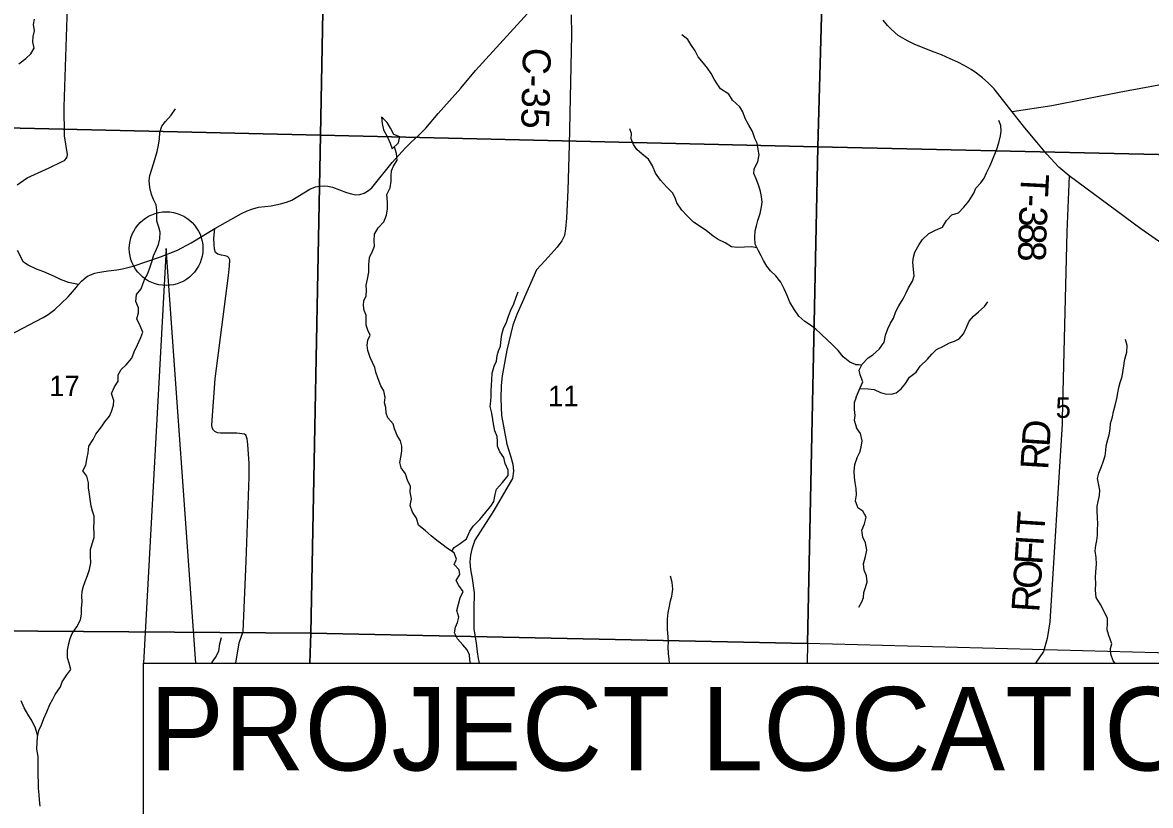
# Model space of a CAD drawing. Extents: x -20.5 to 34, y -66 to 23.9.
# Drawn here: x 3.275 to 5.573, y 15.05 to 16.645 of the extents above; entities that cross this region are included whole.
import ezdxf

# ---------------------------------------------------------------- set-up
doc = ezdxf.new("R2010")
doc.units = 0
for name, color, linetype in [('GM_X_County_Text', 7, 'Continuous'), ('GM_X_Minor_Lake', 7, 'Continuous'), ('GM_X_Minor_River', 7, 'Continuous'), ('GM_X_Minor_River_Text', 7, 'Continuous'), ('GM_X_Section_Text', 7, 'Continuous'), ('GM_X_State_Route', 7, 'Continuous'), ('GM_X_Township_Road', 7, 'Continuous'), ('GM_X_Township_Road_Text', 7, 'Continuous'), ('GM_X_Township_Text', 7, 'Continuous'), ('SH_Text', 7, 'Continuous')]:
    doc.layers.add(name, color=color, linetype=linetype)

msp = doc.modelspace()

# ---------------------------------------------------------------- linework, layer by layer
at = {"layer": 'GM_X_County_Text'}
for points in [[(3.2635, 16.3144), (3.2839, 16.3283), (3.3288, 16.3487), (3.3542, 16.3609), (3.3599, 16.3637), (3.3646, 16.3694), (3.3636, 16.3694), (3.3655, 16.3713), (3.3663, 16.3761), (3.3602, 16.4143), (3.3594, 16.4735), (3.3718, 16.8405), (3.3957, 16.9949), (3.3943, 17.0069), (3.3923, 17.02), (3.3913, 17.0343), (3.3936, 17.0515), (3.396, 17.073), (3.3943, 17.0819)], [(5.6962, 16.5372), (5.5091, 16.5021), (5.372, 16.4751), (5.2911, 16.4627)], [(5.4069, 16.3325), (5.4025, 16.2189), (5.3927, 15.8374)], [(3.7094, 15.34), (3.7163, 15.3814), (3.7239, 15.4048), (3.7302, 15.5476), (3.7366, 15.7189), (3.7361, 15.747), (3.7334, 15.7853), (3.733, 15.7913), (3.7324, 15.7967), (3.7308, 15.8011), (3.7297, 15.8044), (3.7271, 15.8068), (3.7115, 15.8086), (3.6781, 15.8083), (3.672, 15.8093), (3.6665, 15.812), (3.6638, 15.8143), (3.6611, 15.8197), (3.6605, 15.8256), (3.6674, 15.9189), (3.6941, 16.1299), (3.6966, 16.1487), (3.6973, 16.1613), (3.6952, 16.1654), (3.692, 16.1685), (3.6872, 16.1694), (3.6799, 16.1711), (3.6727, 16.173), (3.6681, 16.1762), (3.6654, 16.183), (3.6648, 16.193), (3.6646, 16.2059), (3.6667, 16.2252)], [(3.3886, 16.1111), (3.3681, 16.1151), (3.3519, 16.1215), (3.3395, 16.1275), (3.318, 16.1368), (3.3029, 16.1426), (3.2859, 16.1508), (3.2765, 16.1565), (3.2643, 16.1803)], [(5.3927, 15.8374), (5.3925, 15.8275), (5.3674, 15.4243), (5.3621, 15.3903), (5.3547, 15.3635), (5.3386, 15.34)]]:
    msp.add_lwpolyline(points, dxfattribs=at)
at = {"layer": 'GM_X_Minor_Lake'}
for points in [[(4.5524, 17.4637), (4.898, 17.4556), (4.9246, 17.4548), (4.8948, 16.3916), (3.8817, 16.4153), (3.8974, 17.2409)], [(3.8974, 17.2409), (3.8817, 16.4153), (2.8609, 16.4392), (2.8718, 17.2409)], [(3.8345, 14.5564), (3.829, 14.3877), (2.8293, 14.4033), (2.8417, 15.4083), (3.8622, 15.401), (3.8602, 15.34)], [(3.8602, 15.34), (3.8622, 15.401), (4.8742, 15.38), (4.8734, 15.34)]]:
    msp.add_lwpolyline(points, dxfattribs=at)
for points in [[(4.9246, 17.4548), (5.9103, 17.4412), (5.9082, 17.3615), (5.9397, 17.3613), (5.9209, 16.3687), (4.8948, 16.3916)], [(3.8817, 16.4153), (3.8622, 15.401), (2.8417, 15.4083), (2.8609, 16.4392)], [(4.8948, 16.3916), (4.8742, 15.38), (3.8622, 15.401), (3.8817, 16.4153)], [(4.8948, 16.3916), (5.9209, 16.3687), (5.8926, 15.3531), (4.8742, 15.38)]]:
    msp.add_lwpolyline(points, close=True, dxfattribs=at)
at = {"layer": 'GM_X_Minor_River'}
for points in [[(4.0087, 16.4498), (4.0062, 16.4523), (4.0076, 16.4391), (4.01, 16.4262), (4.0175, 16.4131), (4.0238, 16.3995), (4.0277, 16.3875)], [(4.0277, 16.3875), (4.0404, 16.3998), (4.0436, 16.412), (4.0314, 16.4171), (4.024, 16.4295), (4.0174, 16.4415), (4.0087, 16.4498)]]:
    msp.add_lwpolyline(points, dxfattribs=at)
at = {"layer": 'GM_X_Minor_River_Text'}
for points in [[(3.2673, 16.561), (3.2815, 16.5714), (3.2916, 16.5811), (3.2986, 16.5926), (3.2957, 16.6054), (3.2966, 16.6168), (3.2987, 16.6278), (3.297, 16.6411), (3.2987, 16.6517)], [(4.9718, 15.9482), (4.9602, 15.9533), (4.9464, 15.9641), (4.9364, 15.9772), (4.9244, 15.9891), (4.9144, 15.9977), (4.901, 16.0111), (4.8906, 16.0204), (4.8799, 16.0282), (4.8684, 16.0363), (4.8561, 16.0467), (4.8475, 16.0598), (4.8378, 16.0756), (4.8323, 16.0892), (4.8264, 16.1023), (4.8193, 16.1159), (4.8096, 16.129), (4.7985, 16.139), (4.7911, 16.1488), (4.7845, 16.16), (4.7798, 16.1698), (4.774, 16.1799), (4.7673, 16.1935), (4.7663, 16.2071), (4.7672, 16.2208), (4.7697, 16.2307), (4.7725, 16.2417), (4.7776, 16.2562), (4.78, 16.2692), (4.7814, 16.2787), (4.78, 16.2904), (4.7783, 16.3006), (4.7747, 16.3123), (4.7696, 16.3266), (4.7645, 16.3371), (4.7651, 16.347), (4.7724, 16.3612), (4.7752, 16.3752), (4.7731, 16.3862), (4.7714, 16.3991), (4.7667, 16.4088), (4.7615, 16.4232), (4.7541, 16.4359), (4.7467, 16.4495), (4.7419, 16.463), (4.7357, 16.4731), (4.721, 16.4865), (4.7133, 16.4993), (4.6964, 16.5096), (4.6898, 16.5198), (4.684, 16.5295), (4.6777, 16.5408), (4.6703, 16.552), (4.6618, 16.5621), (4.6514, 16.5748), (4.6451, 16.5872), (4.6362, 16.6003), (4.6303, 16.6101), (4.6181, 16.6201)], [(3.424, 15.8063), (3.4358, 15.8213), (3.4425, 15.8313), (3.4517, 15.8429), (3.4561, 15.8528), (3.4597, 15.8658), (3.4607, 15.8753), (3.4559, 15.8892), (3.4617, 15.903), (3.4698, 15.9141), (3.4696, 15.9274), (3.4755, 15.9385), (3.4856, 15.9474), (3.4971, 15.9616), (3.5021, 15.9742), (3.5087, 15.9883), (3.5157, 16.0033), (3.5196, 16.0139), (3.5145, 16.0268), (3.5078, 16.0411), (3.511, 16.0536), (3.5112, 16.0639), (3.5053, 16.077), (3.5066, 16.0907), (3.5163, 16.1023), (3.5195, 16.1122), (3.5235, 16.1229), (3.529, 16.1324), (3.533, 16.1431), (3.5384, 16.1595), (3.5412, 16.1698), (3.5474, 16.1832), (3.5514, 16.1927), (3.5543, 16.2045), (3.5548, 16.2178), (3.552, 16.2284), (3.5484, 16.2405), (3.5485, 16.2518), (3.548, 16.2625), (3.547, 16.2738), (3.5416, 16.2847), (3.5372, 16.2949), (3.5339, 16.3088), (3.5326, 16.3232), (3.5339, 16.3335), (3.5379, 16.3465), (3.5422, 16.3594), (3.5458, 16.3705), (3.549, 16.3819), (3.5514, 16.3948), (3.5535, 16.4078), (3.5544, 16.4211), (3.5587, 16.434), (3.5657, 16.4436), (3.5772, 16.4563), (3.5865, 16.469)], [(4.9728, 15.882), (4.9811, 15.9008), (4.9863, 15.9134), (4.9811, 15.927), (4.9791, 15.9368), (4.985, 15.9491), (4.9973, 15.9618), (5.007, 15.9684), (5.0204, 15.9804), (5.0301, 15.9938), (5.0329, 16.0079), (5.0376, 16.0208), (5.0431, 16.0323), (5.049, 16.0427), (5.0541, 16.0564), (5.06, 16.0682), (5.0685, 16.0824), (5.0751, 16.0943), (5.0799, 16.1042), (5.088, 16.1184), (5.0913, 16.1287), (5.0896, 16.1416), (5.0886, 16.1571), (5.0899, 16.167), (5.0928, 16.1773), (5.1017, 16.1926), (5.1079, 16.2033), (5.1214, 16.2149), (5.1345, 16.2219), (5.1488, 16.2282), (5.1573, 16.2416), (5.1677, 16.2532), (5.1817, 16.2572), (5.1925, 16.2691), (5.2029, 16.281), (5.2125, 16.2975), (5.2165, 16.3074), (5.2273, 16.3182), (5.2339, 16.3282), (5.2387, 16.3389), (5.2453, 16.3523), (5.2497, 16.3622), (5.2537, 16.3721), (5.2588, 16.3847), (5.2635, 16.3996), (5.2671, 16.4141), (5.2685, 16.4236), (5.2675, 16.4353), (5.2636, 16.4451)], [(4.7711, 16.1858), (4.7598, 16.188), (4.7454, 16.1874), (4.7307, 16.1868), (4.7189, 16.1881), (4.7059, 16.1962), (4.6922, 16.2028), (4.6818, 16.2098), (4.6677, 16.221), (4.6416, 16.238), (4.6301, 16.2499), (4.6181, 16.2626), (4.6076, 16.2776), (4.6041, 16.2878), (4.5986, 16.2979), (4.5863, 16.3106), (4.5747, 16.324), (4.5642, 16.3379), (4.5583, 16.3533), (4.5497, 16.3668), (4.5367, 16.3765), (4.5263, 16.3865), (4.5197, 16.3963), (4.5149, 16.4083), (4.5151, 16.4186), (4.5116, 16.4284)], [(4.0104, 15.8945), (4.0049, 15.9051), (3.999, 15.919), (3.9946, 15.9326), (3.9925, 15.9424), (3.9831, 15.9627), (3.9779, 15.9771), (3.9766, 15.9877), (3.9783, 15.9979), (3.9827, 16.0079), (3.9784, 16.018), (3.9748, 16.0282), (3.975, 16.0388), (3.9748, 16.0487), (3.9709, 16.0585), (3.9692, 16.0683), (3.9702, 16.0778), (3.9745, 16.0885), (3.9755, 16.0999), (3.9745, 16.1097), (3.9774, 16.1223), (3.9802, 16.1364), (3.9799, 16.1512), (3.9812, 16.1664), (3.9878, 16.1794), (3.9917, 16.1893), (3.9912, 16.2003), (3.9917, 16.2139), (3.9991, 16.2266), (4.011, 16.2393), (4.0164, 16.2523), (4.0181, 16.2652), (4.0182, 16.2789), (4.0165, 16.2948), (4.0238, 16.3082), (4.0255, 16.3215), (4.0256, 16.3332), (4.0266, 16.3427), (4.0302, 16.3522), (4.0376, 16.3649), (4.0366, 16.3781), (4.0322, 16.3918)], [(4.1494, 15.568), (4.1538, 15.5757), (4.1662, 15.5835), (4.1793, 15.5936), (4.1858, 15.6088), (4.1929, 15.6192), (4.2063, 15.6327), (4.2185, 15.6477), (4.2285, 15.66), (4.2348, 15.6696), (4.2376, 15.6833), (4.2404, 15.6944), (4.2527, 15.7079), (4.2638, 15.7225), (4.264, 15.7331), (4.2581, 15.747), (4.2549, 15.7591), (4.2471, 15.7708), (4.242, 15.7817), (4.2422, 15.7915), (4.2417, 15.8018), (4.2366, 15.8135), (4.2345, 15.8233), (4.231, 15.849), (4.2274, 15.863), (4.2284, 15.8736), (4.2293, 15.8831), (4.2295, 15.8941), (4.2301, 15.9063), (4.2307, 15.9173), (4.2316, 15.931), (4.2355, 15.9451), (4.2402, 15.9554), (4.2419, 15.9668), (4.2444, 15.9763), (4.2481, 15.9859), (4.2497, 15.9999), (4.2514, 16.0098), (4.2543, 16.022), (4.2605, 16.0346), (4.2648, 16.0465), (4.2688, 16.0575), (4.2754, 16.072), (4.2804, 16.0858), (4.2844, 16.0961)], [(4.9807, 15.8997), (4.9974, 15.8988), (5.0096, 15.8974), (5.0229, 15.8912), (5.0324, 15.8883), (5.0449, 15.8881), (5.0547, 15.8909), (5.0644, 15.899), (5.0733, 15.9094), (5.0815, 15.9224), (5.0953, 15.9329), (5.1031, 15.9448), (5.1184, 15.9591), (5.1269, 15.9691), (5.137, 15.9787), (5.1509, 15.9858), (5.1633, 15.9924), (5.1731, 15.996), (5.1832, 16.0007), (5.1914, 16.0107), (5.1973, 16.0225), (5.2035, 16.0367), (5.2121, 16.047), (5.2221, 16.0555), (5.2348, 16.0667), (5.2415, 16.0763)], [(5.5008, 15.34), (5.4967, 15.3451), (5.4916, 15.3584), (5.4911, 15.3701), (5.4936, 15.3797), (5.488, 15.3963), (5.4845, 15.4076), (5.485, 15.4217), (5.4849, 15.4312), (5.4786, 15.4451), (5.4708, 15.4598), (5.4623, 15.4738), (5.4606, 15.4885), (5.4611, 15.5026), (5.4609, 15.5147), (5.4615, 15.5258), (5.4624, 15.5417), (5.4619, 15.5554), (5.4602, 15.569), (5.4615, 15.5797), (5.4633, 15.5896), (5.4646, 15.601), (5.4648, 15.612), (5.4654, 15.6234), (5.4648, 15.6367), (5.4643, 15.6496), (5.4637, 15.6595), (5.4663, 15.6694), (5.4691, 15.6816), (5.4697, 15.6926), (5.4673, 15.7028), (5.4648, 15.7164), (5.4677, 15.7267), (5.4731, 15.7409), (5.476, 15.7504), (5.48, 15.7626), (5.4814, 15.7733), (5.4827, 15.7828), (5.4856, 15.7954), (5.4885, 15.8053), (5.4902, 15.8167), (5.4915, 15.8285), (5.4951, 15.8418), (5.4976, 15.8529), (5.5005, 15.8647), (5.504, 15.8792), (5.5061, 15.8906), (5.5082, 15.9012), (5.5111, 15.9119), (5.5147, 15.9237), (5.5172, 15.9371), (5.5206, 15.9591), (5.5242, 15.9736), (5.5251, 15.9873), (5.5215, 15.9994)], [(4.9718, 15.9482), (4.9779, 15.9485), (4.9842, 15.9474)], [(4.1873, 15.34), (4.186, 15.347), (4.1851, 15.3568), (4.1804, 15.367), (4.1715, 15.3771), (4.1607, 15.3894), (4.1548, 15.4019), (4.1565, 15.4133), (4.1605, 15.4228), (4.1638, 15.4335), (4.1594, 15.4471), (4.1665, 15.473), (4.1724, 15.4857), (4.1635, 15.498), (4.1584, 15.5086), (4.1654, 15.5205), (4.1644, 15.5303), (4.154, 15.5408), (4.1588, 15.5518), (4.154, 15.565), (4.1402, 15.5739), (4.1291, 15.5821), (4.1188, 15.5899), (4.1073, 15.5991), (4.0954, 15.6096), (4.0816, 15.6211), (4.0772, 15.6351), (4.0694, 15.6478), (4.0646, 15.661), (4.067, 15.6747), (4.0645, 15.6883), (4.0651, 15.6997), (4.0592, 15.7129), (4.0548, 15.7257), (4.0463, 15.7377), (4.0435, 15.7487), (4.0463, 15.7628), (4.0472, 15.7723), (4.0471, 15.7817), (4.0446, 15.7927), (4.038, 15.8036), (4.0325, 15.8175), (4.0297, 15.8274), (4.0192, 15.8397), (4.0157, 15.8495), (4.0147, 15.8605), (4.0123, 15.8703), (4.0136, 15.8813), (4.0104, 15.8945)], [(4.9728, 15.882), (4.9688, 15.8704), (4.9691, 15.8567), (4.9704, 15.8442), (4.969, 15.8347), (4.9737, 15.8196)], [(4.9741, 15.7574), (4.9806, 15.7697), (4.9832, 15.7801), (4.9854, 15.7927), (4.9822, 15.8075), (4.9737, 15.8196)], [(3.3105, 15.0489), (3.3092, 15.0614), (3.3082, 15.072), (3.3073, 15.0853), (3.307, 15.0982), (3.3065, 15.11), (3.3062, 15.1259), (3.3064, 15.138), (3.3062, 15.1498), (3.3037, 15.1646), (3.3042, 15.179), (3.3052, 15.1893), (3.308, 15.2026), (3.3131, 15.2141), (3.3178, 15.2274), (3.324, 15.2408), (3.3305, 15.2561), (3.3364, 15.2668), (3.3408, 15.2764), (3.3519, 15.2918), (3.3555, 15.3017), (3.3647, 15.3163), (3.3729, 15.327), (3.3693, 15.3402), (3.3664, 15.3508), (3.3662, 15.3664), (3.369, 15.3801), (3.3715, 15.3904), (3.3755, 15.4003), (3.3851, 15.4141), (3.3924, 15.4283), (3.3945, 15.4401), (3.3947, 15.4511), (3.3963, 15.4659), (3.3954, 15.4758), (3.3964, 15.4868), (3.3988, 15.4967), (3.4021, 15.5066), (3.4068, 15.5188), (3.4111, 15.5311), (3.4139, 15.5444), (3.4133, 15.558), (3.4131, 15.5717), (3.4163, 15.5831), (3.4203, 15.5957), (3.4209, 15.6056), (3.4196, 15.6154), (3.4205, 15.6287), (3.4203, 15.6394), (3.4171, 15.6499), (3.4147, 15.6601), (3.4122, 15.6741), (3.4109, 15.684), (3.4087, 15.6972), (3.4093, 15.7075), (3.4057, 15.7207), (3.3976, 15.7315), (3.4034, 15.7434), (3.4066, 15.759), (3.4083, 15.7685), (3.41, 15.7822), (3.4185, 15.7956), (3.424, 15.8063)], [(4.9741, 15.7574), (4.9694, 15.7437), (4.9685, 15.7308), (4.9687, 15.7179), (4.9704, 15.708), (4.9721, 15.6955), (4.9727, 15.683), (4.971, 15.6705), (4.9764, 15.6567)], [(4.9788, 15.4539), (4.9844, 15.4652), (4.9878, 15.4737), (4.9888, 15.484), (4.992, 15.4939), (4.9953, 15.5058), (4.994, 15.5179), (4.9893, 15.5292), (4.9879, 15.5425), (4.9923, 15.557), (4.9951, 15.5703), (4.9918, 15.5851), (4.9868, 15.5968), (4.9843, 15.6108), (4.9898, 15.6238), (4.9933, 15.6375), (4.9864, 15.6493), (4.9764, 15.6567)], [(4.593, 15.34), (4.5918, 15.3479), (4.5908, 15.36), (4.5902, 15.3729), (4.5904, 15.3835), (4.5899, 15.3934), (4.5885, 15.4085), (4.5887, 15.4184), (4.5889, 15.4294), (4.5902, 15.4431), (4.592, 15.4526), (4.5947, 15.4667), (4.5976, 15.4762), (4.5996, 15.4907), (4.5983, 15.504), (4.595, 15.5172)], [(3.6607, 15.34), (3.6611, 15.3422), (3.6677, 15.3518), (3.6743, 15.3644), (3.6767, 15.3793), (3.6799, 15.3922)], [(3.3056, 15.1914), (3.3007, 15.2078), (3.294, 15.2221), (3.2851, 15.2363), (3.278, 15.2491), (3.2721, 15.2631)]]:
    msp.add_lwpolyline(points, dxfattribs=at)
at = {"layer": 'GM_X_State_Route'}
msp.add_lwpolyline([(4.3922, 16.6604), (4.393, 16.62), (4.388, 16.3949), (4.3858, 16.3032), (4.383, 16.2466), (4.3807, 16.2244), (4.3789, 16.2112), (4.3734, 16.2004), (4.3642, 16.1874), (4.3395, 16.1602), (4.3219, 16.141), (4.2923, 16.0746), (4.2819, 16.0505), (4.2735, 16.0282), (4.2613, 15.9778), (4.2517, 15.9256), (4.2501, 15.9053), (4.2488, 15.879), (4.2506, 15.8442), (4.2613, 15.786), (4.2689, 15.7626), (4.2736, 15.7454), (4.2748, 15.7309), (4.2732, 15.716), (4.2596, 15.6928), (4.2347, 15.6513), (4.1959, 15.5904), (4.1899, 15.572), (4.1873, 15.5598), (4.1859, 15.5464), (4.1871, 15.5305), (4.1904, 15.5126), (4.1946, 15.4835), (4.1939, 15.4497), (4.1939, 15.4224), (4.1941, 15.4093), (4.1986, 15.3815), (4.2006, 15.3629), (4.2026, 15.3498), (4.205, 15.34)], dxfattribs=at)
at = {"layer": 'GM_X_Township_Road'}
for points in [[(3.2186, 15.9933), (3.3168, 16.0442), (3.3268, 16.0503), (3.3402, 16.0602), (3.3536, 16.0729), (3.3675, 16.0864), (3.3762, 16.0963), (3.3844, 16.106), (3.3886, 16.1111), (3.3947, 16.1181), (3.3992, 16.1225), (3.4048, 16.1269), (3.4081, 16.1289), (3.4114, 16.1306), (3.4168, 16.1327), (3.4216, 16.1341), (3.4278, 16.1355), (3.4364, 16.1371), (3.4488, 16.139), (3.467, 16.1414), (3.4784, 16.1432), (3.4838, 16.1444), (3.5, 16.1485), (3.5554, 16.1679), (3.5901, 16.1814), (3.6183, 16.1961), (3.6667, 16.2252), (3.7207, 16.256), (3.7324, 16.2611), (3.7436, 16.2655), (3.7556, 16.2686), (3.7815, 16.2719), (3.8005, 16.2758), (3.8123, 16.2789), (3.8232, 16.2831), (3.8602, 16.3056), (3.8712, 16.3102), (3.8796, 16.3119), (3.889, 16.3124), (3.8964, 16.3116), (3.9061, 16.3093), (3.9202, 16.3039), (3.9345, 16.2985), (3.9447, 16.2958), (3.9533, 16.2943), (3.9617, 16.2948), (3.9708, 16.2974), (3.9797, 16.3025), (3.9866, 16.3083), (4.0274, 16.3599), (4.0552, 16.39), (4.0664, 16.4015), (4.0816, 16.4145), (4.0964, 16.4301), (4.1214, 16.4593), (4.1676, 16.5112), (4.1972, 16.547), (4.318, 16.6789)], [(5.6268, 16.1732), (5.5529, 16.2249), (5.4069, 16.3325), (5.3859, 16.3505), (5.3615, 16.3765), (5.3411, 16.4015), (5.317, 16.4306), (5.2911, 16.4627), (5.2541, 16.5101), (5.2419, 16.5223), (5.2306, 16.5322), (5.2184, 16.5416), (5.2074, 16.5492), (5.1932, 16.5577), (5.1803, 16.5641), (5.1645, 16.5711), (5.1468, 16.5788), (5.1321, 16.5848), (5.106, 16.595), (5.091, 16.6008), (5.0775, 16.6076), (5.0678, 16.6133), (5.0589, 16.6188), (5.0518, 16.6247), (5.0438, 16.6319), (5.0368, 16.6388), (5.0282, 16.65)]]:
    msp.add_lwpolyline(points, dxfattribs=at)
at = {"layer": 'SH_Text'}
for points in [[(3.5672, 16.1844), (3.5212, 15.34), (3.6277, 15.34)], [(3.5212, 15.34), (5.6922, 15.34), (5.6922, 14.5564), (3.5212, 14.5564)]]:
    msp.add_lwpolyline(points, close=True, dxfattribs=at)
msp.add_circle((3.5672, 16.1844), 0.075, dxfattribs=at)

# ---------------------------------------------------------------- texts
at = {"layer": 'GM_X_Section_Text'}
for s, rotation, p in [('T', 267.0845, (5.3096, 16.3383)), ('-', 267.1819, (5.3075, 16.2958)), ('3', 267.4613, (5.3063, 16.2721)), ('8', 268.0162, (5.3047, 16.2366)), ('8', 268.9748, (5.3035, 16.2006)), ('D', 86.227, (5.367, 15.7795)), ('R', 86.5125, (5.3642, 15.733)), ('T', 86.3711, (5.3561, 15.601)), ('F', 86.3675, (5.3522, 15.5395)), ('I', 86.3708, (5.3546, 15.5778)), ('O', 86.3688, (5.349, 15.4896)), ('R', 86.1916, (5.3459, 15.4428))]:
    msp.add_text(s, height=0.0568, rotation=rotation, dxfattribs=at).set_placement(p)
at = {"layer": 'GM_X_Township_Road_Text'}
msp.add_text('C-35', height=0.05682, rotation=268.6273, dxfattribs=at).set_placement((4.2944, 16.594))
at = {"layer": 'GM_X_Township_Text'}
for s, height, p in [('17', 0.04186, (3.329, 15.8839)), ('11', 0.04186, (4.3452, 15.8633)), ('5', 0.0419, (5.3794, 15.8397))]:
    msp.add_text(s, height=height, rotation=0, dxfattribs=at).set_placement(p)
at = {"layer": 'SH_Text'}
msp.add_text('PROJECT LOCATION ', height=0.17, dxfattribs=at).set_placement((3.5335, 15.1214))

doc.saveas('drawing.dxf')
